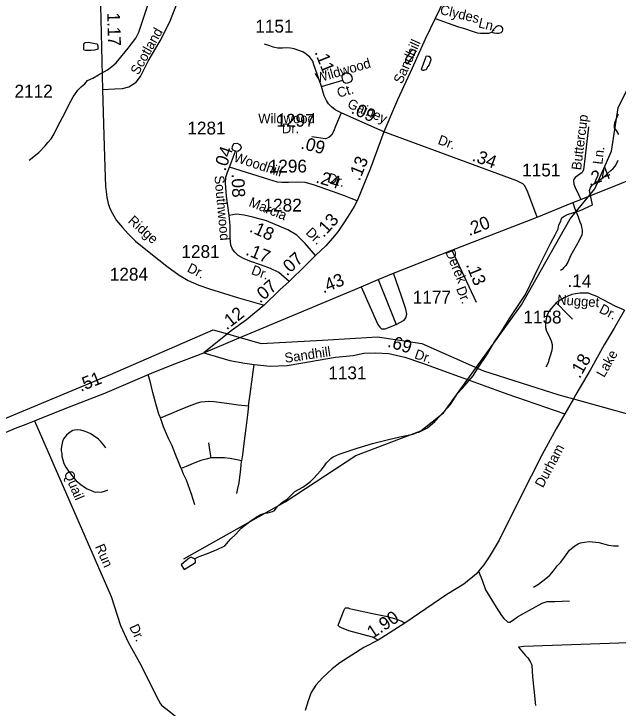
# Model space of a CAD drawing. Extents: x 2206922 to 2357709, y 510027 to 673830.
# Drawn here: x 2278661 to 2284540, y 569360 to 576114 of the extents above; entities that cross this region are included whole.
import ezdxf

# ---------------------------------------------------------------- set-up
doc = ezdxf.new("R2010")
doc.units = 0
for name, color, linetype in [('Exist Boundary Political Urban Extension UEB', 7, 'Continuous'), ('Exist Hydrographic Misc Water Feature', 7, 'Continuous'), ('Exist Road Non-System Type 51', 7, 'Continuous'), ('Exist Road Non-System Type 51 Label', 7, 'Continuous'), ('Exist Road Primary US Attributed', 7, 'Continuous'), ('Exist Road Primary US Mileage Tenths English Label', 7, 'Continuous'), ('Exist Road Secondary Mileage Hundredths English Label', 7, 'Continuous'), ('Exist Road Secondary Type 51 Attributed', 7, 'Continuous'), ('Exist Road Secondary Type 51 Label', 7, 'Continuous'), ('Exist Road Secondary Type 51 Number Label', 7, 'Continuous')]:
    doc.layers.add(name, color=color, linetype=linetype)

msp = doc.modelspace()

# ---------------------------------------------------------------- linework, layer by layer
at = {"layer": 'Exist Boundary Political Urban Extension UEB'}
msp.add_line((2280739, 573000.2), (2280848.5, 572968.9), dxfattribs=at)
for points in [[(2275447.3, 574985.8), (2276902, 573373.2), (2278101, 571907.9), (2278400.8, 572107.7), (2279599.8, 572607.2), (2280599, 573040.1), (2280739, 573000.2)], [(2280848.5, 572968.9), (2281065.3, 572906.9), (2281664.8, 572940.2), (2282197.7, 572973.5), (2282630.6, 572906.9), (2283230.1, 572640.5), (2283962.9, 572407.4), (2284105.3, 572368)], [(2284105.3, 572368), (2285528.2, 571974.5), (2286127.7, 571874.6), (2286722.8, 572028.8)]]:
    msp.add_lwpolyline(points, dxfattribs=at)
at = {"layer": 'Exist Hydrographic Misc Water Feature'}
for points in [[(2278809, 574691.9), (2278902.3, 574766.7), (2278963.8, 574829.6), (2278991.5, 574863.5), (2279023.1, 574898.1), (2279054.5, 574948.1), (2279089.7, 575022.7), (2279134.8, 575106.7), (2279213.6, 575263.6), (2279238.8, 575307.6), (2279284.5, 575372.1), (2279320, 575406.5), (2279349.7, 575434.5), (2279375.6, 575467.1), (2279429.3, 575489.4), (2279484.9, 575521.9), (2279572, 575570.5), (2279614, 575601), (2279655.9, 575637.3), (2279772.1, 575782.4), (2279847, 575879), (2279876.7, 575937.4), (2279903.8, 576013.6), (2279987.2, 576270.3)], [(2279340.5, 575796.3), (2279340.5, 575818.2), (2279345.8, 575830.4), (2279354.2, 575834.4), (2279386, 575839), (2279468, 575821.7), (2279475.8, 575817.7), (2279478.5, 575799.5), (2279476.5, 575769.8), (2279466.4, 575767.6), (2279446.5, 575761.3), (2279412.7, 575757.1), (2279374.7, 575756.7), (2279356.9, 575758.6), (2279344.8, 575762.5), (2279340.7, 575766.3), (2279340.5, 575772.4), (2279340.7, 575776.5), (2279340.5, 575796.3)], [(2282513.1, 575738.1), (2282478, 575687.8), (2282471.6, 575665.7), (2282470.2, 575653.7), (2282470.2, 575644), (2282473.9, 575637.7), (2282480.1, 575631.9), (2282492.6, 575632.1), (2282505.9, 575646.3), (2282523.5, 575678.5), (2282557.6, 575716.8), (2282559.2, 575726.7), (2282567.2, 575738.9), (2282567.2, 575748.6), (2282567.2, 575758.7), (2282552.8, 575762.5), (2282543.2, 575760.3), (2282531.1, 575756.5), (2282523.1, 575754.4), (2282513.1, 575738.1)], [(2282708.1, 575638.2), (2282700.1, 575618.3), (2282688, 575603.9), (2282684.3, 575600), (2282680.4, 575592), (2282670.8, 575571.6), (2282660.7, 575567.8), (2282652.7, 575565.8), (2282644.7, 575563.4), (2282636.5, 575563.4), (2282636.9, 575567.4), (2282628.5, 575571.5), (2282628.3, 575577.6), (2282645.9, 575627.6), (2282667.5, 575689.7), (2282671.6, 575701.7), (2282681.2, 575705.9), (2282691.5, 575703.9), (2282701.3, 575704.1), (2282709.3, 575693.9), (2282715.5, 575684.1), (2282715.9, 575666.2), (2282713.6, 575656), (2282708.1, 575638.2)], [(2280315.7, 570810.8), (2281300.8, 571368), (2281988.8, 571816.5), (2282618.9, 572056.4), (2282841.8, 572232.2), (2283598.8, 573282.8), (2284073.7, 574119.3), (2284312.8, 574412.9), (2284475.8, 574780.2), (2284538.8, 575198.7), (2284783.8, 575692.2)], [(2284545.8, 574939.6), (2284525.2, 574979.6), (2284511.3, 574995.5), (2284505.2, 575005.3), (2284503.1, 575015.4), (2284503.1, 575033.2), (2284508.8, 575057.5), (2284516.2, 575073.4), (2284518.3, 575083.2), (2284526.3, 575103.5), (2284538, 575127.7), (2284541.9, 575143.4)], [(2280418.3, 570811.1), (2280464.6, 570833.7), (2280546.2, 570864.4), (2280589.7, 570883), (2280631.9, 570899.3), (2280713.1, 570938.2), (2280768.9, 571002.4), (2280820.4, 571051), (2280873.3, 571111.6), (2280970.7, 571186.1), (2281026.4, 571224.8), (2281062.3, 571242.9), (2281102.1, 571257.6), (2281130.2, 571259.8), (2281175.9, 571272), (2281191.7, 571280.2), (2281225.5, 571320.5), (2281267, 571358.9), (2281319.1, 571391.6), (2281393.9, 571466.2), (2281473.5, 571509), (2281517.3, 571541.3), (2281546.9, 571565.3), (2281582.3, 571599.7), (2281608.4, 571628.2), (2281651.6, 571676.4), (2281681.6, 571718.5), (2281700.9, 571744.8), (2281721.2, 571766.9), (2281744.9, 571787.3), (2281768.5, 571803.6), (2281824.3, 571832.1), (2282001.5, 571887.7), (2282150.9, 571932.9), (2282292.6, 571970.3), (2282414.4, 571999.5), (2282546.1, 572026.7), (2282582, 572040.7), (2282601.9, 572045), (2282631.8, 572059.6), (2282685.5, 572085.9), (2282756.7, 572148.6), (2282804.2, 572199.1), (2282909.2, 572313.8), (2282977.9, 572420.6), (2283025.3, 572472.7), (2283128.4, 572593.8), (2283173.5, 572666.1), (2283268.3, 572806.7), (2283331.2, 572913.3), (2283404.4, 573023.9), (2283483, 573150.8), (2283638.6, 573384), (2283771.9, 573659.1), (2283885.9, 573886.1), (2283926.9, 573964.7), (2283954.8, 574024.5), (2283964.2, 574060.8), (2283982.1, 574098.7), (2283985.8, 574111.1), (2283993.3, 574129), (2284005.2, 574141), (2284046.9, 574161.5), (2284170.5, 574202.5), (2284290.1, 574255.9), (2284262.6, 574395.4), (2284270.6, 574425.5), (2284286.2, 574447.5), (2284294.4, 574453.5), (2284319.8, 574474), (2284361.6, 574500.2), (2284381.5, 574512.6), (2284411, 574536.9), (2284439.3, 574563.1), (2284468.7, 574589.1), (2284490.6, 574611.3), (2284510.5, 574631.4), (2284526.3, 574661.5), (2284539.8, 574689.8)], [(2279554.8, 571892.6), (2279536.5, 571918.4), (2279504.5, 571956.1), (2279484.5, 571977.8), (2279433.8, 572013.4), (2279409.8, 572027.1), (2279379.9, 572041), (2279345.4, 572054.7), (2279311.4, 572064.2), (2279283.7, 572066), (2279255.2, 572063.8), (2279233.7, 572059.3), (2279199.6, 572039.3), (2279173.8, 572016.8), (2279144.1, 571978.7), (2279134.2, 571952.6), (2279127, 571922.5), (2279121.1, 571886.5), (2279119.7, 571864.4), (2279126, 571836.3), (2279128.1, 571808.4), (2279136.5, 571776.8), (2279148.4, 571738.8), (2279165, 571703.1), (2279191.4, 571665.1), (2279239.8, 571603.8), (2279268.1, 571570), (2279310.8, 571534.3), (2279346.9, 571510.7), (2279375, 571493.1), (2279405.3, 571479.1), (2279434.8, 571465.8), (2279450.8, 571461.8), (2279477.1, 571463.9), (2279509.1, 571462.3), (2279543.3, 571470.5), (2279562.6, 571476.9), (2279574.7, 571482.8)], [(2283715.5, 570536.2), (2283765.1, 570566.9), (2283836.3, 570619.4), (2283876.1, 570654), (2283911.5, 570696), (2283949.3, 570748.4), (2283983.1, 570781), (2284016.7, 570827), (2284067.6, 570895.6), (2284117.6, 570939.9), (2284149.4, 570958.2), (2284175, 570968.6), (2284210.9, 570975), (2284260.9, 570981.2), (2284353, 570970.2), (2284445.3, 570944.9), (2284494.9, 570939.5), (2284543.1, 570939.9)], [(2280418.3, 570811.1), (2280406.6, 570819.4), (2280400.2, 570823.2), (2280392.6, 570825.1), (2280386.5, 570824.8), (2280378.5, 570824.8), (2280364.7, 570818.8), (2280348.7, 570804.6), (2280315.1, 570776.4), (2280287.2, 570752.2), (2280317.8, 570708.2), (2280427.1, 570777.3), (2280427.3, 570783.4), (2280426.9, 570793.2), (2280425, 570805.2), (2280418.3, 570811.1)]]:
    msp.add_lwpolyline(points, dxfattribs=at)
at = {"layer": 'Exist Road Non-System Type 51'}
for p, q in [((2281653.5, 575407.9), (2281860.5, 575469.5)), ((2282204.1, 573528.5), (2282380.2, 573092.5))]:
    msp.add_line(p, q, dxfattribs=at)
for points in [[(2279521.8, 575378.5), (2279644.6, 575385.7), (2279718.6, 575389.3), (2279778.2, 575403.8), (2279849.5, 575451.3), (2279893.8, 575505), (2279966.1, 575653.1), (2280083.4, 575851.9), (2280179.2, 576038), (2280253.2, 576229.5), (2280292.9, 576333.4), (2280392.2, 576501.5), (2280428.4, 576544.8), (2280506, 576634.3), (2280563.8, 576723.7), (2280601.7, 576832.1)], [(2282759.3, 576068.6), (2282976.4, 575990.2), (2283054.8, 575967.8), (2283128.6, 575943.2), (2283168.9, 575929.7), (2283200.3, 575925.3), (2283280.9, 575927.5), (2283310, 575936.5)], [(2283310, 575936.5), (2283331.7, 575930.9), (2283358.2, 575928.2), (2283376.6, 575926.8), (2283390, 575929.1), (2283401.2, 575933.6), (2283408.9, 575939), (2283415.6, 575947), (2283417.4, 575957.8), (2283418.7, 575968.6), (2283414.7, 575978.4), (2283404.8, 575990.6), (2283395, 575996.4), (2283383.7, 575997.3), (2283372.1, 575996.8), (2283362.2, 575993.7), (2283351, 575985.6), (2283333.5, 575968.6), (2283320.1, 575954.7), (2283312.9, 575944.3), (2283310, 575936.5)], [(2281860.5, 575469.5), (2281854.3, 575495.5), (2281856.3, 575515.4), (2281868, 575531.6), (2281891.9, 575539.7), (2281913.9, 575540), (2281934.1, 575528.2), (2281950.2, 575502.3), (2281952.4, 575476.3), (2281938.8, 575454.2), (2281916.8, 575442), (2281892.9, 575435.9), (2281870.9, 575447.5), (2281860.5, 575469.5)], [(2284250, 575016.6), (2284209.7, 574647.7), (2284202.2, 574600), (2284188.8, 574571.6), (2284121.7, 574523.8), (2284111.2, 574508.9), (2284105.2, 574492.5), (2284108.2, 574456.6), (2284120.2, 574423.8), (2284159, 574350.6), (2284176.9, 574307.3)], [(2280816.6, 574777.7), (2280792.4, 574787.6), (2280784.3, 574803.6), (2280788.1, 574823.5), (2280793.9, 574839.5), (2280805.7, 574853.7), (2280831.8, 574858), (2280855.9, 574844.1), (2280870, 574828.2), (2280872.2, 574810.4), (2280860.4, 574788.2), (2280840.6, 574776), (2280816.6, 574777.7)], [(2284098.1, 574277.7), (2284114.9, 574225.9), (2284149.3, 574140.8), (2284168.7, 574091.5), (2284179.1, 574063.2), (2284183.6, 574039.3), (2284191, 574012.4), (2284191, 573991.5), (2284188.1, 573964.6), (2284165.7, 573921.3), (2284129.9, 573857.1), (2284080.6, 573767.5), (2284050.8, 573698.8), (2284029.9, 573666), (2284012, 573646.6), (2283994.1, 573628.7), (2283980.6, 573616.7)], [(2282380.2, 573092.5), (2282457.8, 573133.2), (2282475.7, 573155.4), (2282483.2, 573193.4), (2282472.8, 573241.2), (2282431.6, 573368.8), (2282353.5, 573590.1)], [(2282041, 573459.1), (2282202.3, 573092.9), (2282220.6, 573067), (2282236.7, 573051.3), (2282258.6, 573049.4), (2282272.6, 573049.5), (2282380.2, 573092.5)], [(2283938.2, 573303.7), (2283914.6, 573276.2), (2283890.4, 573250.7), (2283868.7, 573222.6), (2283854.6, 573198.3), (2283844.4, 573166.4), (2283835.5, 573125.6), (2283834.2, 573086), (2283833, 573063), (2283842.5, 573027.9), (2283869.3, 572978.1), (2283887.2, 572933.4), (2283897.4, 572899), (2283897.4, 572865.8), (2283892.3, 572830), (2283879.5, 572786.6), (2283866.8, 572749.6), (2283857.8, 572718.9), (2283836.1, 572678.1)], [(2283938.2, 573303.7), (2283974.6, 573267.3), (2284016.7, 573222.6), (2284069, 573170.2), (2284095.8, 573144.7)], [(2280945, 572300.1), (2280958.7, 572413.2), (2280982.5, 572583.4), (2280997.5, 572701.4)], [(2280087.2, 572184.4), (2280070.7, 572220.6), (2280046.8, 572311.7), (2280012.5, 572429.6), (2279985.7, 572540.1), (2279966.3, 572602.9)], [(2280087.2, 572184.4), (2280196.9, 572230.3), (2280272.7, 572262.2), (2280394.4, 572310.1), (2280446.3, 572330.1), (2280482.2, 572340.1), (2280522.1, 572342), (2280558, 572346), (2280605.9, 572342), (2280731.6, 572328.1), (2280843.3, 572312.1), (2280945, 572300.1)], [(2280945, 572300.1), (2280933, 572212.3), (2280919.1, 572082.6), (2280899.1, 571934.9), (2280885.2, 571823.1), (2280875.2, 571767.2)], [(2278861.5, 572154.8), (2279606.6, 570445.9), (2279698, 570162.7), (2279774.3, 570000.8), (2279897.9, 569774.5), (2280047.8, 569473.1), (2280088.6, 569402), (2280100.5, 569386.2), (2280138.6, 569354.6), (2280458.2, 569102), (2281077.7, 568616.3), (2281222.4, 568516.3), (2281301.3, 568455.8), (2281359.2, 568429.4), (2281397.4, 568418.3)], [(2280289.4, 571690.6), (2280267.8, 571740.3), (2280233.8, 571826.1), (2280201.9, 571911.9), (2280164, 571983.8), (2280118.1, 572097.5), (2280087.2, 572184.4)], [(2280578.9, 571794.2), (2280567, 571874), (2280559, 571941.9)], [(2280578.9, 571794.2), (2280533.1, 571782.2), (2280481.2, 571770.2), (2280437.3, 571754.2), (2280383.5, 571730.3), (2280335.6, 571710.3), (2280289.4, 571690.6)], [(2280875.2, 571767.2), (2280830.3, 571776.2), (2280764.5, 571788.2), (2280708.6, 571794.2), (2280654.8, 571794.2), (2280616.9, 571796.2), (2280578.9, 571794.2)], [(2280831.3, 571447.9), (2280841.3, 571497.8), (2280853.2, 571551.6), (2280865.2, 571657.4), (2280871.2, 571721.3), (2280875.2, 571767.2)], [(2280289.4, 571690.6), (2280307.7, 571638.5), (2280337.6, 571580.6), (2280384.5, 571445.9), (2280418.4, 571342.1)], [(2283182.2, 570691), (2283215.4, 570604.2), (2283249.2, 570510.3), (2283352.6, 570340.5), (2283404.9, 570260.1), (2283427.8, 570230.7), (2283463.6, 570200.1), (2283472.5, 570196.3), (2283485.3, 570197.5), (2283512.1, 570212.9), (2283560.5, 570247.3), (2283614, 570275.7), (2283800.4, 570381.4), (2283850.2, 570395.4), (2283925.5, 570395.4), (2284067.1, 570403.1)], [(2282205.4, 570019.8), (2282150.9, 570048.7), (2281920.9, 570112), (2281848.5, 570142.3), (2281830.3, 570151.8), (2281823, 570156.2), (2281819.2, 570160), (2281817.4, 570162.3), (2281817.2, 570166.3), (2281818.3, 570172.6), (2281819, 570177.8), (2281820.9, 570183.1), (2281874.7, 570317.4), (2281879.6, 570330.4), (2281887.4, 570334.8), (2281900, 570336.4), (2281911.9, 570334.7), (2281927.6, 570329.8), (2281955.3, 570321.1), (2282150.9, 570278.9), (2282279.8, 570254.7), (2282365.3, 570233), (2282434.2, 570206.2), (2282464.8, 570187)], [(2285749, 570033.8), (2283621, 569959.9), (2283571.1, 569953.5), (2283633.7, 569876), (2283661.9, 569848.3), (2283684.2, 569814.6), (2283692.4, 569794.7), (2283698.8, 569772.7), (2283707.8, 569664.8), (2283720.9, 569543), (2283736.3, 569385.3)]]:
    msp.add_lwpolyline(points, dxfattribs=at)
at = {"layer": 'Exist Road Primary US Attributed'}
msp.add_line((2282923.1, 573815.8), (2283750.8, 574137.8), dxfattribs=at)
for points in [[(2283750.8, 574137.8), (2284098.1, 574277.7), (2284176.9, 574307.3), (2284967.3, 574626.3)], [(2280508.6, 572815.6), (2280853.2, 572963.5), (2281419.8, 573199.4), (2282041, 573459.1), (2282204.1, 573528.5), (2282353.5, 573590.1), (2282923.1, 573815.8)], [(2278063.5, 571722.8), (2278176.7, 571803.7), (2278279.8, 571882.6), (2278369.4, 571933.5), (2278472.7, 571992.4), (2278562.4, 572035.2), (2278676.2, 572082.4), (2278780.3, 572123), (2278861.5, 572154.8), (2279159.9, 572274.9), (2279544.7, 572425.1), (2280000, 572618.5), (2280201.1, 572698.2), (2280508.6, 572815.6)]]:
    msp.add_lwpolyline(points, dxfattribs=at)
at = {"layer": 'Exist Road Secondary Type 51 Attributed'}
for p, q in [((2282261.3, 574966.5), (2281843.7, 575152.6)), ((2280758.8, 574624.1), (2280816.6, 574777.7))]:
    msp.add_line(p, q, dxfattribs=at)
for points in [[(2279450.1, 578573.1), (2279474.9, 577161), (2279500.1, 576334.3), (2279521.8, 575378.5), (2279536.3, 574929.5), (2279545.3, 574624.1), (2279552.5, 574436.2), (2279565.1, 574331.4), (2279579.6, 574269.9), (2279595.8, 574219.3), (2279621.1, 574172.4), (2279660.9, 574105.5), (2279716.8, 574036.8), (2279772.8, 573975.4), (2279845.1, 573903.1), (2279993.1, 573783.9), (2280150.3, 573660.1), (2280269.4, 573571.6), (2280357.9, 573520.1), (2280460.9, 573474.9), (2280563.8, 573438.8), (2280845.5, 573352), (2281096.5, 573279.8)], [(2283881.3, 578436.3), (2283863.3, 578405.6), (2283787.4, 578270.1), (2283722.4, 578138.2), (2283567.1, 577805.7), (2283121.1, 576835.4), (2282982, 576535.6), (2282759.3, 576068.6), (2282663, 575869.3), (2282535.4, 575587.1), (2282394.4, 575278), (2282261.3, 574966.5)], [(2281843.7, 575152.6), (2281785.5, 575181.7), (2281752, 575208.5), (2281720.6, 575237.7), (2281702.7, 575271.3), (2281678.1, 575316.1), (2281653.5, 575407.9), (2281608.7, 575537.8), (2281579.6, 575618.4), (2281568.4, 575654.3), (2281539.3, 575694.6), (2281505.7, 575721.4), (2281472.2, 575743.8), (2281434.1, 575759.5), (2281387.1, 575773), (2281351.3, 575779.7), (2281317.7, 575784.2), (2281272.9, 575781.9), (2281230.4, 575781.9), (2281201.3, 575786.4), (2281183.4, 575790.9), (2281149.8, 575804.3), (2281098.3, 575820)], [(2281843.7, 575152.6), (2281792.3, 575029.4), (2281769.9, 574968.9), (2281749.7, 574933.1), (2281725.1, 574910.7), (2281691.5, 574897.2), (2281559.5, 574919.6)], [(2282261.3, 574966.5), (2282131.4, 574611.7), (2281999.5, 574295.2)], [(2283750.8, 574137.8), (2283709.8, 574250.6), (2283653.1, 574396.9), (2283629.2, 574444.7), (2283611.3, 574461.1), (2283555.6, 574488.4), (2282261.3, 574966.5)], [(2280757, 574153.4), (2280729.9, 574342.2), (2280720.9, 574466.9), (2280724.5, 574524.7), (2280740.8, 574575.3), (2280758.8, 574624.1)], [(2281999.5, 574295.2), (2281943.5, 574318.7), (2281878.5, 574344), (2281759.3, 574387.4), (2281576.9, 574452.4), (2281493.8, 574474.1), (2281423.4, 574477.7), (2281331.3, 574472.3), (2281266.3, 574474.1), (2281226.6, 574477.7), (2281139.9, 574503), (2280758.8, 574624.1)], [(2281999.5, 574295.2), (2281970.6, 574239.2), (2281929.1, 574170.6), (2281878.5, 574091.1), (2281811.7, 573993.5), (2281761.1, 573932), (2281696.1, 573858), (2281596.8, 573763.1)], [(2281596.8, 573763.1), (2281493.8, 573878.7), (2281412.6, 573961.9), (2281327.7, 574014.3), (2281118.2, 574099.2), (2280986.4, 574137.1), (2280901.5, 574157), (2280825.7, 574164.2), (2280757, 574153.4)], [(2281338.5, 573511.9), (2281239.2, 573596.9), (2281157.9, 573638.4), (2281071.3, 573671), (2280957.5, 573708.9), (2280896.1, 573734.2), (2280841.9, 573763.1), (2280811.2, 573795.6), (2280787.7, 573824.5), (2280771.5, 573862.5), (2280764.3, 573934.8), (2280764.3, 574054), (2280757, 574153.4)], [(2282923.1, 573815.8), (2283157.4, 573309.8)], [(2281596.8, 573763.1), (2281497.5, 573665.5), (2281338.5, 573511.9)], [(2281338.5, 573511.9), (2281248.2, 573428.8), (2281096.5, 573279.8)], [(2284600.4, 573232.2), (2284509.8, 573271.7), (2284401.4, 573329.2), (2284327.4, 573366.2), (2284281.5, 573384.1), (2284252.1, 573395.6), (2284215.1, 573398.1), (2284169.2, 573396.8), (2284124.5, 573391.7), (2284090.1, 573382.8), (2284051.8, 573368.8), (2284013.5, 573350.9), (2283982.9, 573331.7), (2283954.8, 573316.4), (2283938.2, 573303.7)], [(2281096.5, 573279.8), (2280925, 573136.1), (2280773.3, 573031.3), (2280739, 573000.2), (2280508.6, 572815.6)], [(2284600.4, 573232.2), (2284501.6, 573057.9), (2284405.2, 572893.3), (2284268.1, 572646.8), (2284129.6, 572410), (2284105.3, 572368), (2284020.5, 572221.7)], [(2280508.6, 572815.6), (2280763.2, 572741.7), (2280907.9, 572714.8), (2280997.5, 572701.4), (2281154.2, 572688), (2281318.3, 572692.4), (2281451.1, 572716.3), (2281789.6, 572773.2), (2281963.3, 572790.7), (2282065.1, 572811.6), (2282182.9, 572816.8), (2282308.5, 572811.2), (2282465.1, 572773.6), (2282627.8, 572718.6), (2282994.2, 572584.9), (2283457.6, 572418.4), (2283738.5, 572318.7), (2284020.5, 572221.7)], [(2284020.5, 572221.7), (2283936.9, 572076.8), (2283799.8, 571825.9), (2283585.4, 571405.9), (2283381.3, 570992.3), (2283285.6, 570830.1), (2283232, 570754.8), (2283182.2, 570691), (2283160.6, 570665.1), (2283039.3, 570564.6), (2282874.7, 570464.6), (2282464.8, 570187), (2282205.4, 570019.8), (2282065.5, 569948.8), (2281832.7, 569801.4), (2281757.8, 569742.2), (2281664.4, 569652.7), (2281599.9, 569581.7), (2281553.9, 569513.2), (2281523.6, 569431.6), (2281493.4, 569336.2)]]:
    msp.add_lwpolyline(points, dxfattribs=at)

# ---------------------------------------------------------------- texts
at = {"layer": 'Exist Road Non-System Type 51 Label'}
for s, rotation, p in [('Clydes', 346.31416, (2282799.6, 576114.1)), ('Ln.', 345.86209, (2283173.9, 575984.9)), ('Scotland', 60.7834, (2279871.4, 575513.5)), ('Wildwood', 16.08978, (2281611.6, 575442.1)), ('Ct.', 16.08978, (2281819.5, 575297.9)), ('Buttercup', 82.77005, (2284178.7, 574589.8)), ('Ln.', 82.77005, (2284385.8, 574645)), ('Quail', 293.2559, (2279144.6, 571645.5)), ('Run', 293.2559, (2279449.2, 570932.2)), ('Dr.', 295.50877, (2279781.6, 570149.6))]:
    msp.add_text(s, height=95, rotation=rotation, dxfattribs=at).set_placement(p)
at = {"layer": 'Exist Road Primary US Mileage Tenths English Label'}
for s, rotation, p in [('.24', 21.29131, (2284261.9, 574435.8)), ('.20', 21.70461, (2283089.7, 573951.3)), ('.43', 22.33285, (2281672, 573393.3)), ('.51', 21.68344, (2279311.4, 572437))]:
    msp.add_text(s, height=125, rotation=rotation, dxfattribs=at).set_placement(p)
at = {"layer": 'Exist Road Secondary Mileage Hundredths English Label'}
for s, rotation, p in [('1.17', 271.76221, (2279568.1, 576125.5)), ('.11', 291.98922, (2281584.4, 575742.1)), ('.09', 336.30018, (2281933.3, 575150.3)), ('.09', 345.54516, (2281444.5, 574804.6)), ('.04', 71.1465, (2280718.2, 574578.7)), ('.34', 339.75807, (2283110.6, 574687.9)), ('.13', 67.75311, (2282023.7, 574481.9)), ('.24', 343.86594, (2281591.2, 574475)), ('.08', 272.33003, (2280777.7, 574557.4)), ('.13', 47.82639, (2281673.8, 573931.9)), ('.18', 335.59697, (2280945, 573998.6)), ('.17', 338.11025, (2280907.9, 573772.8)), ('.07', 43.26291, (2281316.5, 573558.3)), ('.13', 291.9936, (2283057.3, 573674)), ('.14', 357.86739, (2284045.2, 573459.1)), ('.07', 40.34384, (2281054.8, 573293.9)), ('.12', 38.0444, (2280731.1, 573033.6)), ('.69', 342.60102, (2282288.4, 572877.3)), ('.18', 60.42386, (2284165.6, 572559.4)), ('1.90', 33.58179, (2282148.7, 570031.5))]:
    msp.add_text(s, height=125, rotation=rotation, dxfattribs=at).set_placement(p)
at = {"layer": 'Exist Road Secondary Type 51 Label'}
for s, rotation, p in [('Sandhill', 65.85779, (2282436.2, 575426)), ('Gainey', 336.30018, (2281897.7, 575207.1)), ('Dr.', 339.75807, (2282778.8, 574851)), ('Woodhill', 341.71044, (2280791.6, 574681.5)), ('Dr.', 342.09746, (2281703.9, 574479.7)), ('Southwood', 275.2463, (2280611.3, 574537.9)), ('Marcia', 338.05478, (2280939.5, 574246.7)), ('Ridge', 318.23014, (2279764.7, 574090.8)), ('Dr.', 315.54692, (2281493.7, 573979.3)), ('Derek', 291.9936, (2282856.7, 573799.1)), ('Dr.', 333.50101, (2280338.4, 573610.5)), ('Dr.', 339.52434, (2280963.1, 573584.9)), ('Dr.', 291.9936, (2282961.3, 573441)), ('Nugget', 356.02113, (2283943.8, 573288.1)), ('Dr.', 332.43649, (2284347.1, 573212.9)), ('Sandhill', 8.33367, (2281301.5, 572719)), ('Dr.', 340.76444, (2282551.1, 572765.3)), ('Lake', 60.42386, (2284403.6, 572569.9)), ('Durham', 62.05207, (2283808.1, 571496.7))]:
    msp.add_text(s, height=95, rotation=rotation, dxfattribs=at).set_placement(p)
for s, p in [('Wildwood', (2281038, 575049.8)), ('Dr.', (2281268.1, 574952.4))]:
    msp.add_text(s, height=95, dxfattribs=at).set_placement(p)
at = {"layer": 'Exist Road Secondary Type 51 Number Label'}
for s, p in [('1151', (2281009.7, 575931.7)), ('2112', (2278667.2, 575299.8)), ('1297', (2281215.4, 575016.8)), ('1281', (2280348.6, 574940.8)), ('1296', (2281140.4, 574570.9)), ('1151', (2283606.1, 574533)), ('1282', (2281090.1, 574191.3)), ('1281', (2280291, 573740)), ('1284', (2279594, 573518.9)), ('1177', (2282541.3, 573295.4)), ('1158', (2283617.6, 573101.9)), ('1131', (2281719.9, 572558.8))]:
    msp.add_text(s, height=125, dxfattribs=at).set_placement(p)

doc.saveas('drawing.dxf')
